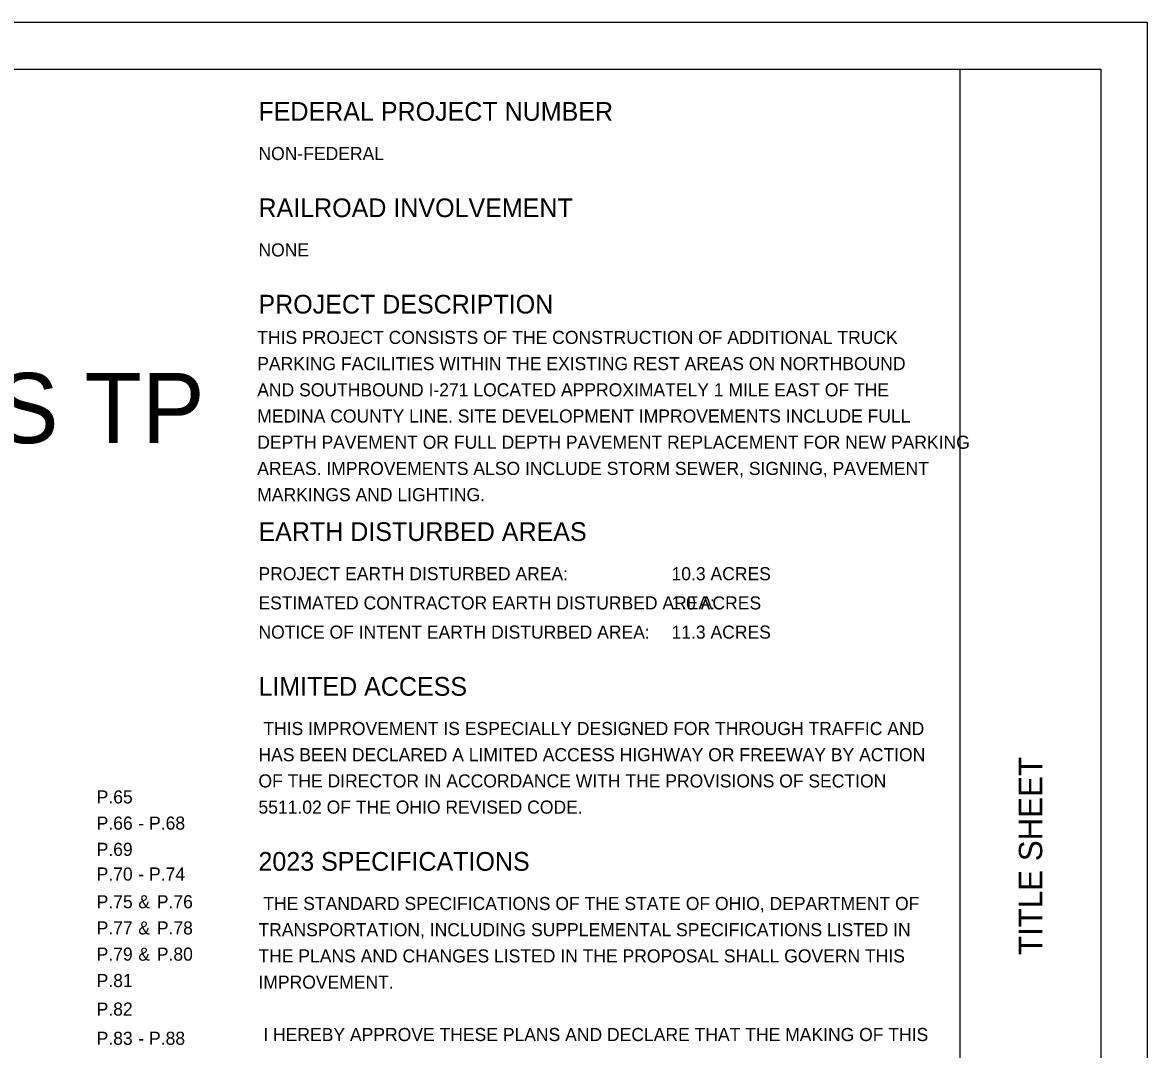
# Model space of a CAD drawing. Extents: x 0 to 34, y 0 to 22.
# Drawn here: x 21.98 to 34, y 11.03 to 22 of the extents above; entities that cross this region are included whole.
import ezdxf

# ---------------------------------------------------------------- set-up
doc = ezdxf.new("R2010")
doc.units = 0
for name, color, linetype in [('Default', 7, 'Continuous'), ('SH_Border', 7, 'Continuous'), ('SH_Cut_Line', 7, 'Continuous'), ('SH_Data', 7, 'Continuous'), ('SH_Text', 7, 'Continuous')]:
    doc.layers.add(name, color=color, linetype=linetype)

msp = doc.modelspace()

# ---------------------------------------------------------------- linework, layer by layer
at = {"layer": 'SH_Border'}
msp.add_line((32, 0.5), (32, 21.5), dxfattribs=at)
msp.add_lwpolyline([(1.5, 21.5), (33.5, 21.5), (33.5, 0.5), (1.5, 0.5)], close=True, dxfattribs=at)
at = {"layer": 'SH_Cut_Line'}
msp.add_lwpolyline([(0, 0), (34, 0), (34, 22), (0, 22)], close=True, dxfattribs=at)
at = {"layer": 'SH_Data'}
msp.add_line((24.5, 14.526), (24.5, 14.526), dxfattribs=at)

# ---------------------------------------------------------------- texts
at = {"layer": 'Default'}
for s, p in [('THIS PROJECT CONSISTS OF THE CONSTRUCTION OF ADDITIONAL TRUCK ', (24.487, 18.565)), ('PARKING FACILITIES WITHIN THE EXISTING REST AREAS ON NORTHBOUND ', (24.487, 18.285)), ('AND SOUTHBOUND I-271 LOCATED APPROXIMATELY 1 MILE EAST OF THE ', (24.487, 18.005)), ('MEDINA COUNTY LINE. SITE DEVELOPMENT IMPROVEMENTS INCLUDE FULL ', (24.487, 17.725)), ('DEPTH PAVEMENT OR FULL DEPTH PAVEMENT REPLACEMENT FOR NEW PARKING ', (24.487, 17.445)), ('AREAS. IMPROVEMENTS ALSO INCLUDE STORM SEWER, SIGNING, PAVEMENT ', (24.487, 17.165)), ('MARKINGS AND LIGHTING.', (24.487, 16.885))]:
    msp.add_text(s, height=0.14, dxfattribs=at).set_placement(p)
at = {"layer": 'SH_Data'}
msp.add_text('TITLE SHEET', height=0.25, rotation=90, dxfattribs=at).set_placement((32.875, 12.035))
msp.add_text(' I HEREBY APPROVE THESE PLANS AND DECLARE THAT THE MAKING OF THIS', height=0.14, dxfattribs=at).set_placement((24.5, 11.116))
at = {"layer": 'SH_Text'}
for s, height, p in [('FEDERAL PROJECT NUMBER', 0.2, (24.5, 20.95)), ('NON-FEDERAL', 0.14, (24.5, 20.53)), ('RAILROAD INVOLVEMENT', 0.2, (24.5, 19.92)), ('NONE', 0.14, (24.5, 19.5)), ('PROJECT DESCRIPTION', 0.2, (24.5, 18.89)), ('SUM-IR 271 REST AREAS TP', 0.75, (10.214, 17.505)), ('EARTH DISTURBED AREAS', 0.2, (24.5, 16.46)), ('PROJECT EARTH DISTURBED AREA:', 0.14, (24.5, 16.04)), ('10.3 ACRES', 0.14, (28.914, 16.04)), ('ESTIMATED CONTRACTOR EARTH DISTURBED AREA:', 0.14, (24.5, 15.728)), ('1.0 ACRES', 0.14, (28.914, 15.728)), ('NOTICE OF INTENT EARTH DISTURBED AREA:', 0.14, (24.5, 15.416)), ('11.3 ACRES', 0.14, (28.914, 15.416)), ('LIMITED ACCESS', 0.2, (24.5, 14.806)), (' THIS IMPROVEMENT IS ESPECIALLY DESIGNED FOR THROUGH TRAFFIC AND', 0.14, (24.5, 14.386)), ('HAS BEEN DECLARED A LIMITED ACCESS HIGHWAY OR FREEWAY BY ACTION', 0.14, (24.5, 14.106)), ('OF THE DIRECTOR IN ACCORDANCE WITH THE PROVISIONS OF SECTION', 0.14, (24.5, 13.826)), ('P.65', 0.14, (22.771, 13.655)), ('5511.02 OF THE OHIO REVISED CODE.', 0.14, (24.5, 13.546)), ('P.66', 0.14, (22.771, 13.375)), ('P.68', 0.14, (23.331, 13.375)), (' - ', 0.14, (23.164, 13.375)), ('P.69', 0.14, (22.771, 13.095)), ('2023 SPECIFICATIONS', 0.2, (24.5, 12.936)), ('P.70', 0.14, (22.771, 12.831)), (' - ', 0.14, (23.164, 12.831)), ('P.74', 0.14, (23.331, 12.831)), ('P.75', 0.14, (22.771, 12.535)), (' & ', 0.14, (23.164, 12.535)), ('P.76', 0.14, (23.414, 12.535)), (' THE STANDARD SPECIFICATIONS OF THE STATE OF OHIO, DEPARTMENT OF ', 0.14, (24.5, 12.516)), ('P.77', 0.14, (22.771, 12.255)), (' & ', 0.14, (23.164, 12.255)), ('P.78', 0.14, (23.414, 12.255)), ('TRANSPORTATION, INCLUDING SUPPLEMENTAL SPECIFICATIONS LISTED IN ', 0.14, (24.5, 12.236)), ('P.79', 0.14, (22.771, 11.975)), (' & ', 0.14, (23.164, 11.975)), ('P.80', 0.14, (23.414, 11.975)), ('THE PLANS AND CHANGES LISTED IN THE PROPOSAL SHALL GOVERN THIS ', 0.14, (24.5, 11.956)), ('P.81', 0.14, (22.771, 11.693)), ('IMPROVEMENT.', 0.14, (24.5, 11.676)), ('P.82', 0.14, (22.771, 11.388)), ('P.83', 0.14, (22.771, 11.076)), ('P.88', 0.14, (23.331, 11.076)), (' - ', 0.14, (23.164, 11.076))]:
    msp.add_text(s, height=height, dxfattribs=at).set_placement(p)

doc.saveas('drawing.dxf')
